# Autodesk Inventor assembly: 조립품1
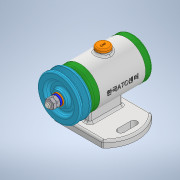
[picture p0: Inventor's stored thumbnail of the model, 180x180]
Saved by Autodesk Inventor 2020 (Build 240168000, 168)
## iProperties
Created: 2021-09
Part Number: 조립품1
Document SubType Name: Assembly
Designer: Administrator
Author: Administrator
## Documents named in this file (14)
- C:\Users\Administrator\Desktop\710906V1013\답안조립품.iam
- C:\Users\Administrator\Desktop\710906V1013\본체.ipt
- C:\Users\Administrator\Desktop\710906V1013\베어링 15x32x9.ipt
- C:\Users\Administrator\Desktop\710906V1013\앞커버.ipt
- C:\Users\Administrator\Desktop\710906V1013\뒤커버.ipt
- C:\Users\Administrator\Desktop\710906V1013\캡.ipt
- C:\Users\Administrator\Desktop\710906V1013\오일 실 15x25x7.ipt
- C:\Users\Administrator\Desktop\710906V1013\볼트 M4x12.ipt
- C:\Users\Administrator\Desktop\710906V1013\축.ipt
- C:\Users\Administrator\Desktop\710906V1013\키 3x3.ipt
- C:\Users\Administrator\Desktop\710906V1013\V벨트풀리.ipt
- C:\Users\Administrator\Desktop\710906V1013\와셔 8x17.ipt
- C:\Users\Administrator\Desktop\710906V1013\스프링와셔 8.ipt
- C:\Users\Administrator\Desktop\710906V1013\너트 M8.ipt
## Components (1 placed, 1 different names)
1. V벨트풀리:1
